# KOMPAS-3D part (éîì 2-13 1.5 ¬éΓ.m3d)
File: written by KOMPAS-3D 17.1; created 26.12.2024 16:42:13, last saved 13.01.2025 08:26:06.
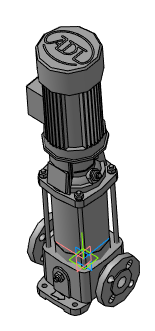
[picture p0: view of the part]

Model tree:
1. Операция без истории:3
2. Эскиз:1
3. Элемент выдавливания:1  (labels: ВМН 2-13 1.5 кВт)
     Расстояние 2 = 250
